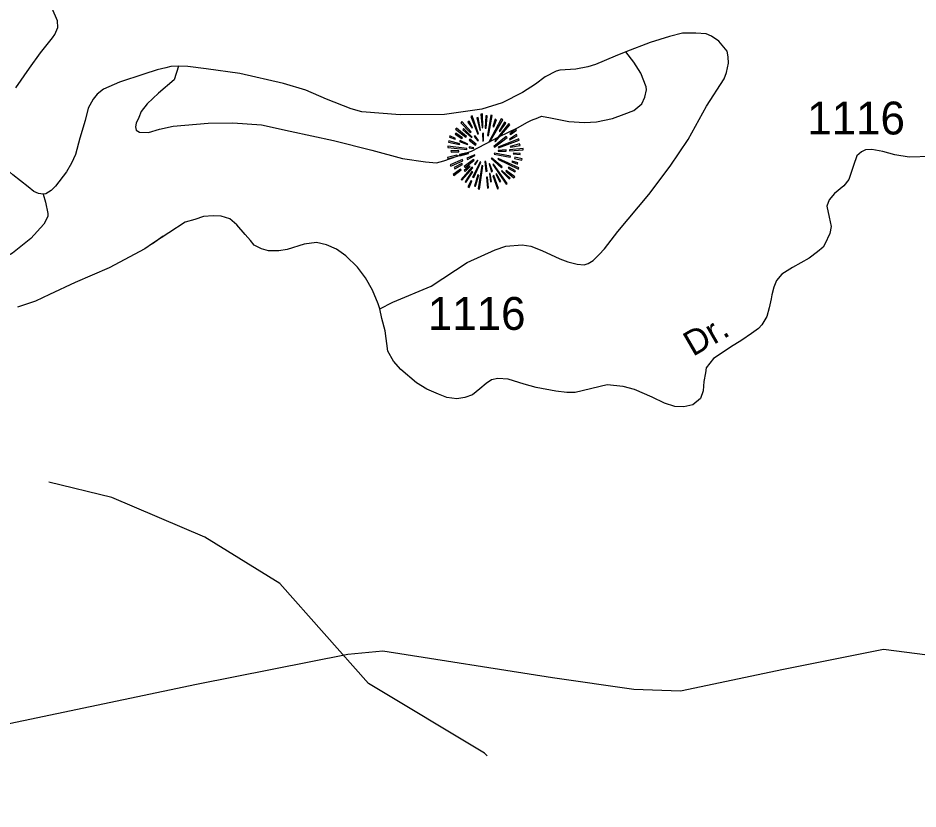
# Model space of a CAD drawing. Extents: x 990631 to 1056237, y 535999 to 585651.
# Drawn here: x 1018534 to 1021960, y 543237 to 546248 of the extents above; entities that cross this region are included whole.
import ezdxf

# ---------------------------------------------------------------- set-up
doc = ezdxf.new("R2010")
doc.units = 0
for name, color, linetype in [('Exist Boundary Political StateLine', 7, 'Continuous'), ('Exist Geographical Mountain Summit CELL', 7, 'Continuous'), ('Exist Hydrographic Misc Water Feature', 7, 'Continuous'), ('Exist Road Non-System Type 51', 7, 'Continuous'), ('Exist Road Secondary Type 41 Attributed', 7, 'Continuous'), ('Exist Road Secondary Type 51 Attributed', 7, 'Continuous'), ('Exist Road Secondary Type 51 Label', 7, 'Continuous'), ('Exist Road Secondary Type 51 Number Label', 7, 'Continuous')]:
    doc.layers.add(name, color=color, linetype=linetype)

msp = doc.modelspace()

# ---------------------------------------------------------------- linework, layer by layer
at = {"layer": 'Exist Boundary Political StateLine'}
msp.add_lwpolyline([(1017281.6, 543236.7), (1017534.9, 543325.4), (1017750.2, 543407.8), (1018275.8, 543515.5), (1019213, 543712), (1019789.3, 543826), (1019922.3, 543838.7), (1020568.2, 543737.3), (1020878.5, 543692.9), (1021055.8, 543686.6), (1021448.4, 543769), (1021828.4, 543845), (1022271.6, 543788)], dxfattribs=at)
at = {"layer": 'Exist Geographical Mountain Summit CELL'}
for points in [[(1020257.9, 545872.7), (1020284.1, 545805.9), (1020287, 545806.9), (1020263, 545875.3)], [(1020296.5, 545882.1), (1020300.5, 545830.2), (1020303.7, 545830.6), (1020302.3, 545883.2)], [(1020312.5, 545828), (1020316.4, 545828), (1020320, 545875.3), (1020314.6, 545875.3)], [(1020324.5, 545799.6), (1020339.3, 545876.7), (1020333.9, 545878.5), (1020321.2, 545800.4)], [(1020219.4, 545849.5), (1020255.4, 545812), (1020258.7, 545814.5), (1020223.4, 545854.2)], [(1020247, 545850.9), (1020262.6, 545829.1), (1020264.5, 545830.6), (1020251, 545854.9)], [(1020291.7, 545820.8), (1020294.3, 545821.5), (1020285.2, 545869.4), (1020280.8, 545868.3)], [(1020327.7, 545777.9), (1020330.6, 545776.1), (1020379.3, 545860.7), (1020373.8, 545864.4)], [(1020342.2, 545834.9), (1020345.5, 545833.8), (1020355, 545860.7), (1020350.2, 545862.5)], [(1020348.8, 545779.3), (1020351, 545777.1), (1020406.6, 545841.4), (1020402.5, 545846.2)], [(1020386.2, 545850.9), (1020365.1, 545817.5), (1020368.1, 545816.3), (1020390.5, 545847.7)], [(1020198, 545805.9), (1020223.8, 545789.5), (1020226, 545792.1), (1020200.9, 545809.8)], [(1020199.1, 545824.7), (1020238.7, 545794.2), (1020240.9, 545796.4), (1020202.7, 545829.1)], [(1020227.4, 545821.8), (1020260.1, 545792.8), (1020262.3, 545794.9), (1020230.3, 545826.9)], [(1020301.9, 545808.8), (1020303.3, 545779.7), (1020305.9, 545780), (1020305.9, 545809.1)], [(1020406.6, 545784.4), (1020434.1, 545799.3), (1020431.3, 545804.4), (1020405.1, 545786.9)], [(1020406.6, 545807.3), (1020408.4, 545804.8), (1020431.3, 545821.1), (1020427.6, 545824.7)], [(1020173.3, 545775.7), (1020214.7, 545766.2), (1020215.8, 545769.5), (1020174.4, 545780.4)], [(1020176.2, 545794.9), (1020198.7, 545786.2), (1020199.8, 545789.2), (1020177.6, 545800)], [(1020214.7, 545777.9), (1020245.2, 545765.9), (1020246.3, 545768), (1020216.9, 545781.9)], [(1020251, 545783.3), (1020276.1, 545764.4), (1020278.2, 545767.3), (1020253.6, 545786.5)], [(1020270.7, 545796.4), (1020284.5, 545780), (1020286.6, 545782.2), (1020273.9, 545799.3)], [(1020345.5, 545759.3), (1020347.3, 545756.8), (1020396, 545792.8), (1020392.8, 545797.1)], [(1020362.5, 545756.4), (1020363.7, 545754.2), (1020441.8, 545782.9), (1020440, 545787.6)], [(1020170.7, 545754.6), (1020242.7, 545747.7), (1020243, 545750.6), (1020170.7, 545759.6)], [(1020182.8, 545737.2), (1020212.5, 545738.6), (1020212.5, 545742.2), (1020181.6, 545742.2)], [(1020215.1, 545728.1), (1020216.1, 545723.4), (1020249.2, 545731.7), (1020248.5, 545735.4)], [(1020251.4, 545753.5), (1020268.5, 545751.3), (1020268.9, 545753.5), (1020252.1, 545757.8)], [(1020361.5, 545743.7), (1020361.5, 545740.8), (1020391.7, 545740.8), (1020392.4, 545745.9)], [(1020404.7, 545742.6), (1020457.1, 545745.9), (1020457.4, 545750.6), (1020405.1, 545745.9)], [(1020408.4, 545756.4), (1020445.1, 545763), (1020443.6, 545768.4), (1020407, 545758.6)], [(1020169.3, 545716.8), (1020170.7, 545711.7), (1020206.7, 545722.3), (1020204.5, 545725.5)], [(1020179, 545689.1), (1020181.6, 545684.5), (1020227.1, 545704.4), (1020225.6, 545709.2)], [(1020232.8, 545682.7), (1020235.7, 545679), (1020270.3, 545707.4), (1020268.5, 545709.9)], [(1020242.7, 545713.9), (1020244.9, 545709.2), (1020273.6, 545724.4), (1020272.5, 545727.7)], [(1020271.4, 545692.1), (1020274.6, 545689.1), (1020284.8, 545705.5), (1020283, 545707)], [(1020311.4, 545701.2), (1020315.3, 545664.2), (1020319.7, 545664.4), (1020314.6, 545701.9)], [(1020335.7, 545712.8), (1020374.2, 545677.5), (1020376.8, 545681.9), (1020337.5, 545715)], [(1020346.9, 545729.9), (1020407.7, 545717.9), (1020408.8, 545722.3), (1020348, 545733.5)], [(1020360.7, 545710.3), (1020438.9, 545672.1), (1020440.7, 545677.5), (1020362.3, 545713.2)], [(1020414.2, 545700.1), (1020435.3, 545692.1), (1020437.1, 545696.5), (1020415.6, 545703.3)], [(1020419.6, 545730.6), (1020446.2, 545728.4), (1020446.2, 545732.8), (1020420, 545733.8)], [(1020423.7, 545713.5), (1020452, 545706.2), (1020452.7, 545711.7), (1020424.7, 545717.9)], [(1020190.3, 545652.5), (1020193.2, 545648.5), (1020221.6, 545669.6), (1020219, 545672.8)], [(1020196.5, 545673.2), (1020225.6, 545689.9), (1020223.4, 545693.6), (1020194.3, 545678.3)], [(1020221.2, 545632.8), (1020224.1, 545630.3), (1020264.9, 545677.9), (1020261.9, 545680.1)], [(1020236.5, 545664.2), (1020255.8, 545682.3), (1020252.4, 545684.5), (1020232.1, 545667.4)], [(1020264.5, 545642.7), (1020268.9, 545640.9), (1020295.4, 545699.3), (1020292.9, 545700.1)], [(1020285.9, 545597.3), (1020290.6, 545596.2), (1020303.3, 545685.5), (1020300.1, 545686.3)], [(1020327.4, 545692.5), (1020336.1, 545662.6), (1020340.1, 545664.4), (1020329.5, 545693.6)], [(1020341.9, 545690.2), (1020392.4, 545615.4), (1020396, 545618.3), (1020344.4, 545691.4)], [(1020374.2, 545664.4), (1020404.3, 545635.4), (1020407.7, 545638), (1020376.4, 545667)], [(1020390.9, 545665.2), (1020421.4, 545639.4), (1020424.7, 545643), (1020392.8, 545667.8)], [(1020400, 545676.1), (1020425.1, 545663), (1020427.6, 545666.7), (1020402.2, 545680.1)], [(1020261.2, 545664.2), (1020236.1, 545624.9), (1020239.3, 545622.3), (1020265.2, 545661.9)], [(1020276.1, 545607.4), (1020288.1, 545650.3), (1020284.5, 545650.7), (1020271.7, 545608.4)], [(1020317.5, 545642.7), (1020321.2, 545600.2), (1020325.2, 545601.2), (1020321.8, 545642.7)], [(1020337.1, 545626), (1020331.7, 545655.8), (1020328.4, 545655.8), (1020332.8, 545624.9)], [(1020341.9, 545647.4), (1020359.3, 545597.6), (1020363.7, 545599.4), (1020344.8, 545648.1)], [(1020352.4, 545653.2), (1020368.4, 545623.7), (1020372.4, 545626), (1020356.1, 545654.7)], [(1020246.3, 545605.6), (1020251, 545602.7), (1020261.9, 545627.4), (1020258.7, 545629.6)]]:
    msp.add_lwpolyline(points, close=True, dxfattribs=at)
at = {"layer": 'Exist Hydrographic Misc Water Feature'}
msp.add_lwpolyline([(1020320, 543438.5), (1020310.2, 543449.2), (1019868.8, 543714.1), (1019531, 544095.1), (1019245.1, 544271.5), (1018891.7, 544423), (1018651.6, 544480.4)], dxfattribs=at)
at = {"layer": 'Exist Road Non-System Type 51'}
for points in [[(1018525.6, 545982.5), (1018578.1, 546056.9), (1018620.1, 546115.5), (1018634.7, 546135), (1018666, 546172.2), (1018674.5, 546185.8), (1018685.4, 546211.4), (1018684.1, 546237.4), (1018663.7, 546284.3)], [(1019911.9, 545141), (1019960.3, 545165.6), (1020107.4, 545227.4), (1020244.4, 545316.9), (1020350.2, 545365.3), (1020390.7, 545379.9), (1020452.8, 545383.9), (1020486.7, 545378.8), (1020528.2, 545363.3), (1020597.2, 545331.1), (1020626.8, 545320.1), (1020662.6, 545310.8), (1020688.6, 545308.1), (1020704.7, 545313.6), (1020723.1, 545324.8), (1020745.8, 545348.1), (1020766.6, 545369.5), (1020816.8, 545435.7), (1020935.6, 545576), (1021017.2, 545683.4), (1021084.7, 545785.1), (1021154.9, 545912.9), (1021222.4, 546016.7), (1021231.3, 546040.4), (1021238.4, 546076.2), (1021237.3, 546100.3), (1021233.9, 546122.3), (1021201.3, 546159.4), (1021173.9, 546178.4), (1021154, 546187.2), (1021114.1, 546190.4), (1021064.1, 546190.2), (1021013.6, 546177.8), (1020940.9, 546154.3), (1020847.6, 546119.3)], [(1019144.8, 546064.1), (1019128.9, 546012.6), (1019069.3, 545962.4), (1019025.9, 545921.8), (1019002.9, 545892.7), (1018994, 545868.9), (1018983.4, 545847.3), (1018980.9, 545833.3), (1018984.4, 545821.2), (1018996.3, 545812.8), (1019030.3, 545811.7), (1019072.7, 545824.3), (1019125.2, 545836.6), (1019257.7, 545848.1), (1019351.7, 545849), (1019461.6, 545841.4), (1019570.7, 545817.6), (1019735.7, 545782.1), (1019880.6, 545745.3), (1019997.5, 545713.4), (1020085.1, 545700.4), (1020127.1, 545696.9), (1020155.4, 545704.2), (1020260.6, 545740.7), (1020364.5, 545795.2), (1020437.8, 545830.7), (1020470.4, 545849.7), (1020488.8, 545859.1), (1020513, 545868.2), (1020527.3, 545873.7), (1020561, 545868.6), (1020630.8, 545854.2), (1020690.5, 545850.2), (1020736.8, 545852.9), (1020797, 545864.9), (1020841.8, 545881.4), (1020878.3, 545896.1), (1020909, 545921), (1020919.9, 545946.8), (1020926.9, 545974.5), (1020925.3, 545986.5), (1020904.9, 546037.4), (1020878.4, 546080.1), (1020847.6, 546119.3)], [(1020847.6, 546119.3), (1020807, 546102.6), (1020732, 546071.1), (1020703.6, 546062), (1020657.4, 546053.6), (1020597.1, 546049.6), (1020583, 546046.1), (1020540.2, 546023.5), (1020503.4, 545996.6), (1020454.1, 545964.2), (1020376.9, 545924.8), (1020300, 545901.3), (1020157.2, 545880.2), (1019989.1, 545879.8), (1019843.3, 545890.5), (1019801.7, 545902), (1019708.8, 545939.1), (1019630.1, 545973.9), (1019544.8, 545998.6), (1019377.9, 546036.2), (1019250.4, 546054.5), (1019180.8, 546062.8), (1019144.8, 546064.1)], [(1019144.8, 546064.1), (1019116.5, 546063), (1019096.4, 546057.7), (1019064.3, 546050.7), (1019013.7, 546034.3), (1018920.5, 546003.4), (1018859.5, 545977.4), (1018835, 545958.3), (1018820.4, 545938.8), (1018801.3, 545905.4), (1018789.5, 545857.8), (1018769.3, 545790.4), (1018753.3, 545728.9), (1018738.2, 545695.4), (1018718.9, 545661.9), (1018677.2, 545607.4), (1018660.7, 545591.9), (1018640.2, 545578.5), (1018630.2, 545576.9)], [(1018630.2, 545576.9), (1018612.3, 545579.5), (1018594.4, 545588), (1018573, 545604.9), (1018514.5, 545650.7), (1018448.4, 545709), (1018277.6, 545866.9), (1018246.5, 545893.9), (1018232.6, 545900.2), (1018220.9, 545904.7), (1018194.7, 545903.6), (1018164.6, 545900.6), (1018118.1, 545884.1), (1018026.7, 545847.2), (1017835.7, 545759.4)], [(1018630.2, 545576.9), (1018639.2, 545546.5), (1018647.7, 545504.1), (1018647.3, 545492.1), (1018632.3, 545462.6), (1018582.4, 545408.4), (1018512.7, 545352.6), (1018453.4, 545318.6), (1018396.4, 545290.5), (1018346.1, 545278.1), (1018315.8, 545273.1), (1018287.8, 545274.1), (1018263.9, 545276.8), (1018224.7, 545298.2), (1018160.3, 545348.3), (1018144.8, 545366.8)]]:
    msp.add_lwpolyline(points, dxfattribs=at)
at = {"layer": 'Exist Road Secondary Type 41 Attributed'}
msp.add_lwpolyline([(1019046.2, 545389.9), (1019017.3, 545369.3), (1018881.4, 545297.4), (1018751.4, 545241.7), (1018653.9, 545195.5), (1018601, 545169.5), (1018531.7, 545147.3)], dxfattribs=at)
at = {"layer": 'Exist Road Secondary Type 51 Attributed'}
for points in [[(1022008.7, 545720.2), (1021926.3, 545718.5), (1021871.9, 545727), (1021826, 545739.7), (1021784.4, 545747.4), (1021760.6, 545746.5), (1021745.3, 545738.9), (1021726.6, 545723.6), (1021713.9, 545687), (1021696.9, 545633.5), (1021677.3, 545609.7), (1021641.6, 545580.4), (1021621.5, 545556.4), (1021613.4, 545532.3), (1021621.5, 545490.4), (1021628.9, 545454.6), (1021624.7, 545427.4), (1021605.6, 545387.4), (1021599.4, 545375.7), (1021577.9, 545357.3), (1021545.6, 545333.9), (1021482.8, 545298.6), (1021442, 545273.1), (1021421.6, 545248.5), (1021411.4, 545223), (1021403.1, 545194), (1021400.6, 545178.3), (1021393.5, 545144.4), (1021384.2, 545111.2), (1021365.5, 545079.8), (1021352.8, 545066.2), (1021326.4, 545046.6), (1021289.9, 545021.2), (1021245.7, 544994.4), (1021210.1, 544971.4), (1021182, 544951.9), (1021154, 544916.2), (1021150.6, 544896.6), (1021144.6, 544864.3), (1021142.1, 544828.6), (1021132, 544799.7), (1021103.1, 544775.6), (1021069, 544768.3), (1021033.9, 544769.1), (1020995.1, 544781.9), (1020948.4, 544804.9), (1020881.3, 544833.7), (1020837.1, 544845.6), (1020776.6, 544851.2), (1020655.3, 544821.9), (1020623.8, 544821.9), (1020581.4, 544827), (1020506.5, 544841.5), (1020461.4, 544854.4), (1020399.6, 544872.8), (1020360.5, 544875.8), (1020336.7, 544869.9), (1020316.3, 544856.3), (1020291.7, 544836.7), (1020264.5, 544813.8), (1020234.7, 544802.7), (1020205, 544798.5), (1020166.8, 544802.7), (1020134.5, 544816.3), (1020090.3, 544835), (1020050.4, 544859.7), (1019991.8, 544910.2), (1019962.9, 544941.7), (1019942.5, 544979.1), (1019931.7, 545057.1), (1019919.2, 545103.5), (1019911.9, 545141), (1019905.1, 545159.7), (1019883, 545212.4)], [(1019883, 545212.4), (1019856.7, 545258.3), (1019826.9, 545299.9), (1019781.9, 545342.8), (1019746.2, 545368.3), (1019708, 545384.5), (1019670.6, 545393), (1019623.9, 545387), (1019559.3, 545366.1), (1019527.1, 545361.3), (1019488, 545362), (1019461.2, 545369.3), (1019433.6, 545383.4), (1019419.2, 545401.1), (1019398.8, 545423.2), (1019367.3, 545460.1), (1019340.1, 545483.9), (1019307.8, 545494.1), (1019276.4, 545495), (1019239.9, 545492.4), (1019206.7, 545480.5), (1019170.1, 545470.7), (1019046.2, 545389.9), (1019086.8, 545418.8)]]:
    msp.add_lwpolyline(points, dxfattribs=at)

# ---------------------------------------------------------------- texts
at = {"layer": 'Exist Road Secondary Type 51 Label'}
msp.add_text('Dr.', height=95, rotation=30.0879, dxfattribs=at).set_placement((1021103.2, 544957.5))
at = {"layer": 'Exist Road Secondary Type 51 Number Label'}
for p in [(1021538.3, 545804.7), (1020094.2, 545060.8)]:
    msp.add_text('1116', height=125, dxfattribs=at).set_placement(p)

doc.saveas('drawing.dxf')
